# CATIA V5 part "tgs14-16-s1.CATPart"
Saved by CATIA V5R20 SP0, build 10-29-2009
Part number: TGS14-16-S1
Revision: 1
Definition: design
Nomenclature: TGS14-16-S1
Source: made
Description: NOT SPECIFIED
Bounding box of the stored display mesh (mm): x -22 to 0.8, y 0 to 14, z -6 to 6
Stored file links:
  C:\Users\Raffaele\Desktop\3D X SITO CF\I-MOLD\TGS-S1\tgs14-s1.step\tgs14-16-s1.CATPart
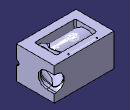
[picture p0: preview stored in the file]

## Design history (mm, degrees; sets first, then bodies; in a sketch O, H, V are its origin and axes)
Set1
  Line1 "LINE #4065": stored without definition
  DatumCurve1 "COMPOSITE_CURVE #4118"
  DatumCurve2 "COMPOSITE_CURVE #4169"
  DatumCurve3 "COMPOSITE_CURVE #4248"
  DatumCurve4 "COMPOSITE_CURVE #4291"
  DatumCurve5 "COMPOSITE_CURVE #4520"
  DatumCurve6 "COMPOSITE_CURVE #4661"
  DatumCurve7 "COMPOSITE_CURVE #4688"
  DatumCurve8 "COMPOSITE_CURVE #4746"
  DatumCurve9 "COMPOSITE_CURVE #4801"
  DatumCurve10 "COMPOSITE_CURVE #4830"
  DatumSurface1 "OPEN_SHELL #4055"
Body1 "MANIFOLD_SOLID_BREP #4056" (main body)
  Solid1: solid without history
